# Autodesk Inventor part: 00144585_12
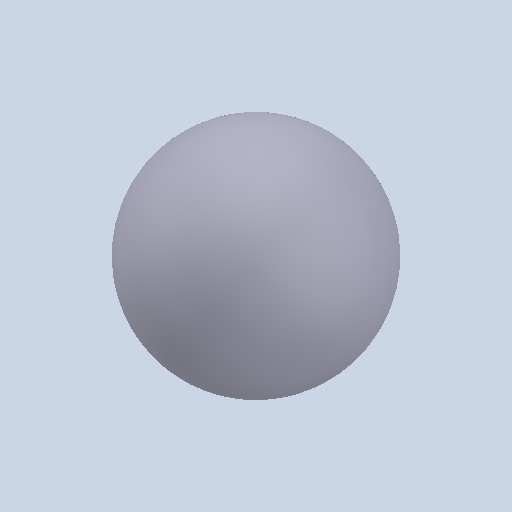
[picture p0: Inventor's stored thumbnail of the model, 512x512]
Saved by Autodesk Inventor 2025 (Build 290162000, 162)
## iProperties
Created: 2021-02
Part Number: 00144585_12
Material: Generico
Document SubType Name: Modeling
Designer: Ryzen5700u
Density: 1 g/cm^3
Appearance: Default
Author: Ryzen5700u
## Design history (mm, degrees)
feature "Solido1"
node "Solido2"
